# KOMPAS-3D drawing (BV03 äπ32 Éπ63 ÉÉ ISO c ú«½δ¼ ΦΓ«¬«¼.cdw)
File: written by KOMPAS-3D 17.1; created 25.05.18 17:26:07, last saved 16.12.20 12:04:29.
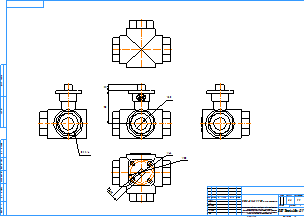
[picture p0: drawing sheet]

Sheet 1: A2, landscape

Title block, sheet 1: name: BV03 Ду32 Ру63 Р/Р ISO c голым штоком; material: Сталь 20  ГОСТ 1050-88; mass: 2,2; sheets: 1; sheet format: A2; stored path: C:\Users\kka\KOMPAS_Work\!Trash\BV3 кран трехходовой шаровой\KOMPAS 2D\BV03 Ду32 Ру63 РР ISO.cdw

Views: Проекционный вид 2, Проекционный вид 6, Проекционный вид 7, Проекционный вид 8, Проекционный вид 9
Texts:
  kka
  adl
  Рама для чертежей
  Лит-Масса-Масштаб
  Материал-Предприятие
  Масштаб
  Изм.
  Лист
  № докум.
  Подп.
  Дата
  Лит.
  Разраб.
  Пров.
  Т.контр.
  Листов
  Внимание! Данный продукт является объектом авторского права ООО «Торговый Дом АДЛ».
  Запрещается изменение, копирование, распространение
  (в том числе путем копирования на другие сайты и ресурсы в Интернете)
  или любое иное использование информации и объектов без предварительного
  согласия правообладателя (ООО «Торговый Дом АДЛ»).
  Н.контр.
  Утв.
  ООО "Торговый дом АДЛ"
  Изменение
  Номер документа
  Подпись
  Обозначение документа
  Наименование изделия
  Масса изделия по ГОСТ 2.109-73
  Порядковый номер листа
  Общее количество листов в документе
  Характер работы, выполненной лицом, подписавшим документ
  Наименование или индекс предприятия, выпускающего документ
  Инв. № подл.
  Подп. и дата
  Взам. инв. №
  Инв. № дубл.
  Инвентарный номер подлинника по ГОСТ 2.501-68
  Подпись принявшего подлинник в отдел технической документации
  Инвентарный номер подлинника, взамен которого выпущен данный подлинник
  Инвентарный номер дубликата по ГОСТ 2.502-68
  Подпись принявшего дубликат в отдел технической документации
  Справ. №
  Перв. примен.
  Обозначение документа, взамен или на основании которого выпущен данный документ
  Обозначение документа, в котором впервые записан данный документ
  Подпись лица, копировавшего чертеж
  Обозначение формата листа
  !Рама для чертежа
Dimensions and other numbers on the sheet: 25; 63; 11; 42; 50; 1:1; 1; 2,2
